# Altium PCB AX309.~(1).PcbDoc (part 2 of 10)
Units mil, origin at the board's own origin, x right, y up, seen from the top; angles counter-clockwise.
Board outline 5185 x 3614 mil, 4 copper layers (Top Layer, GND, Mid-Layer 1, Bottom Layer); 191 components, 352 nets, 1106 pads, 425 vias.
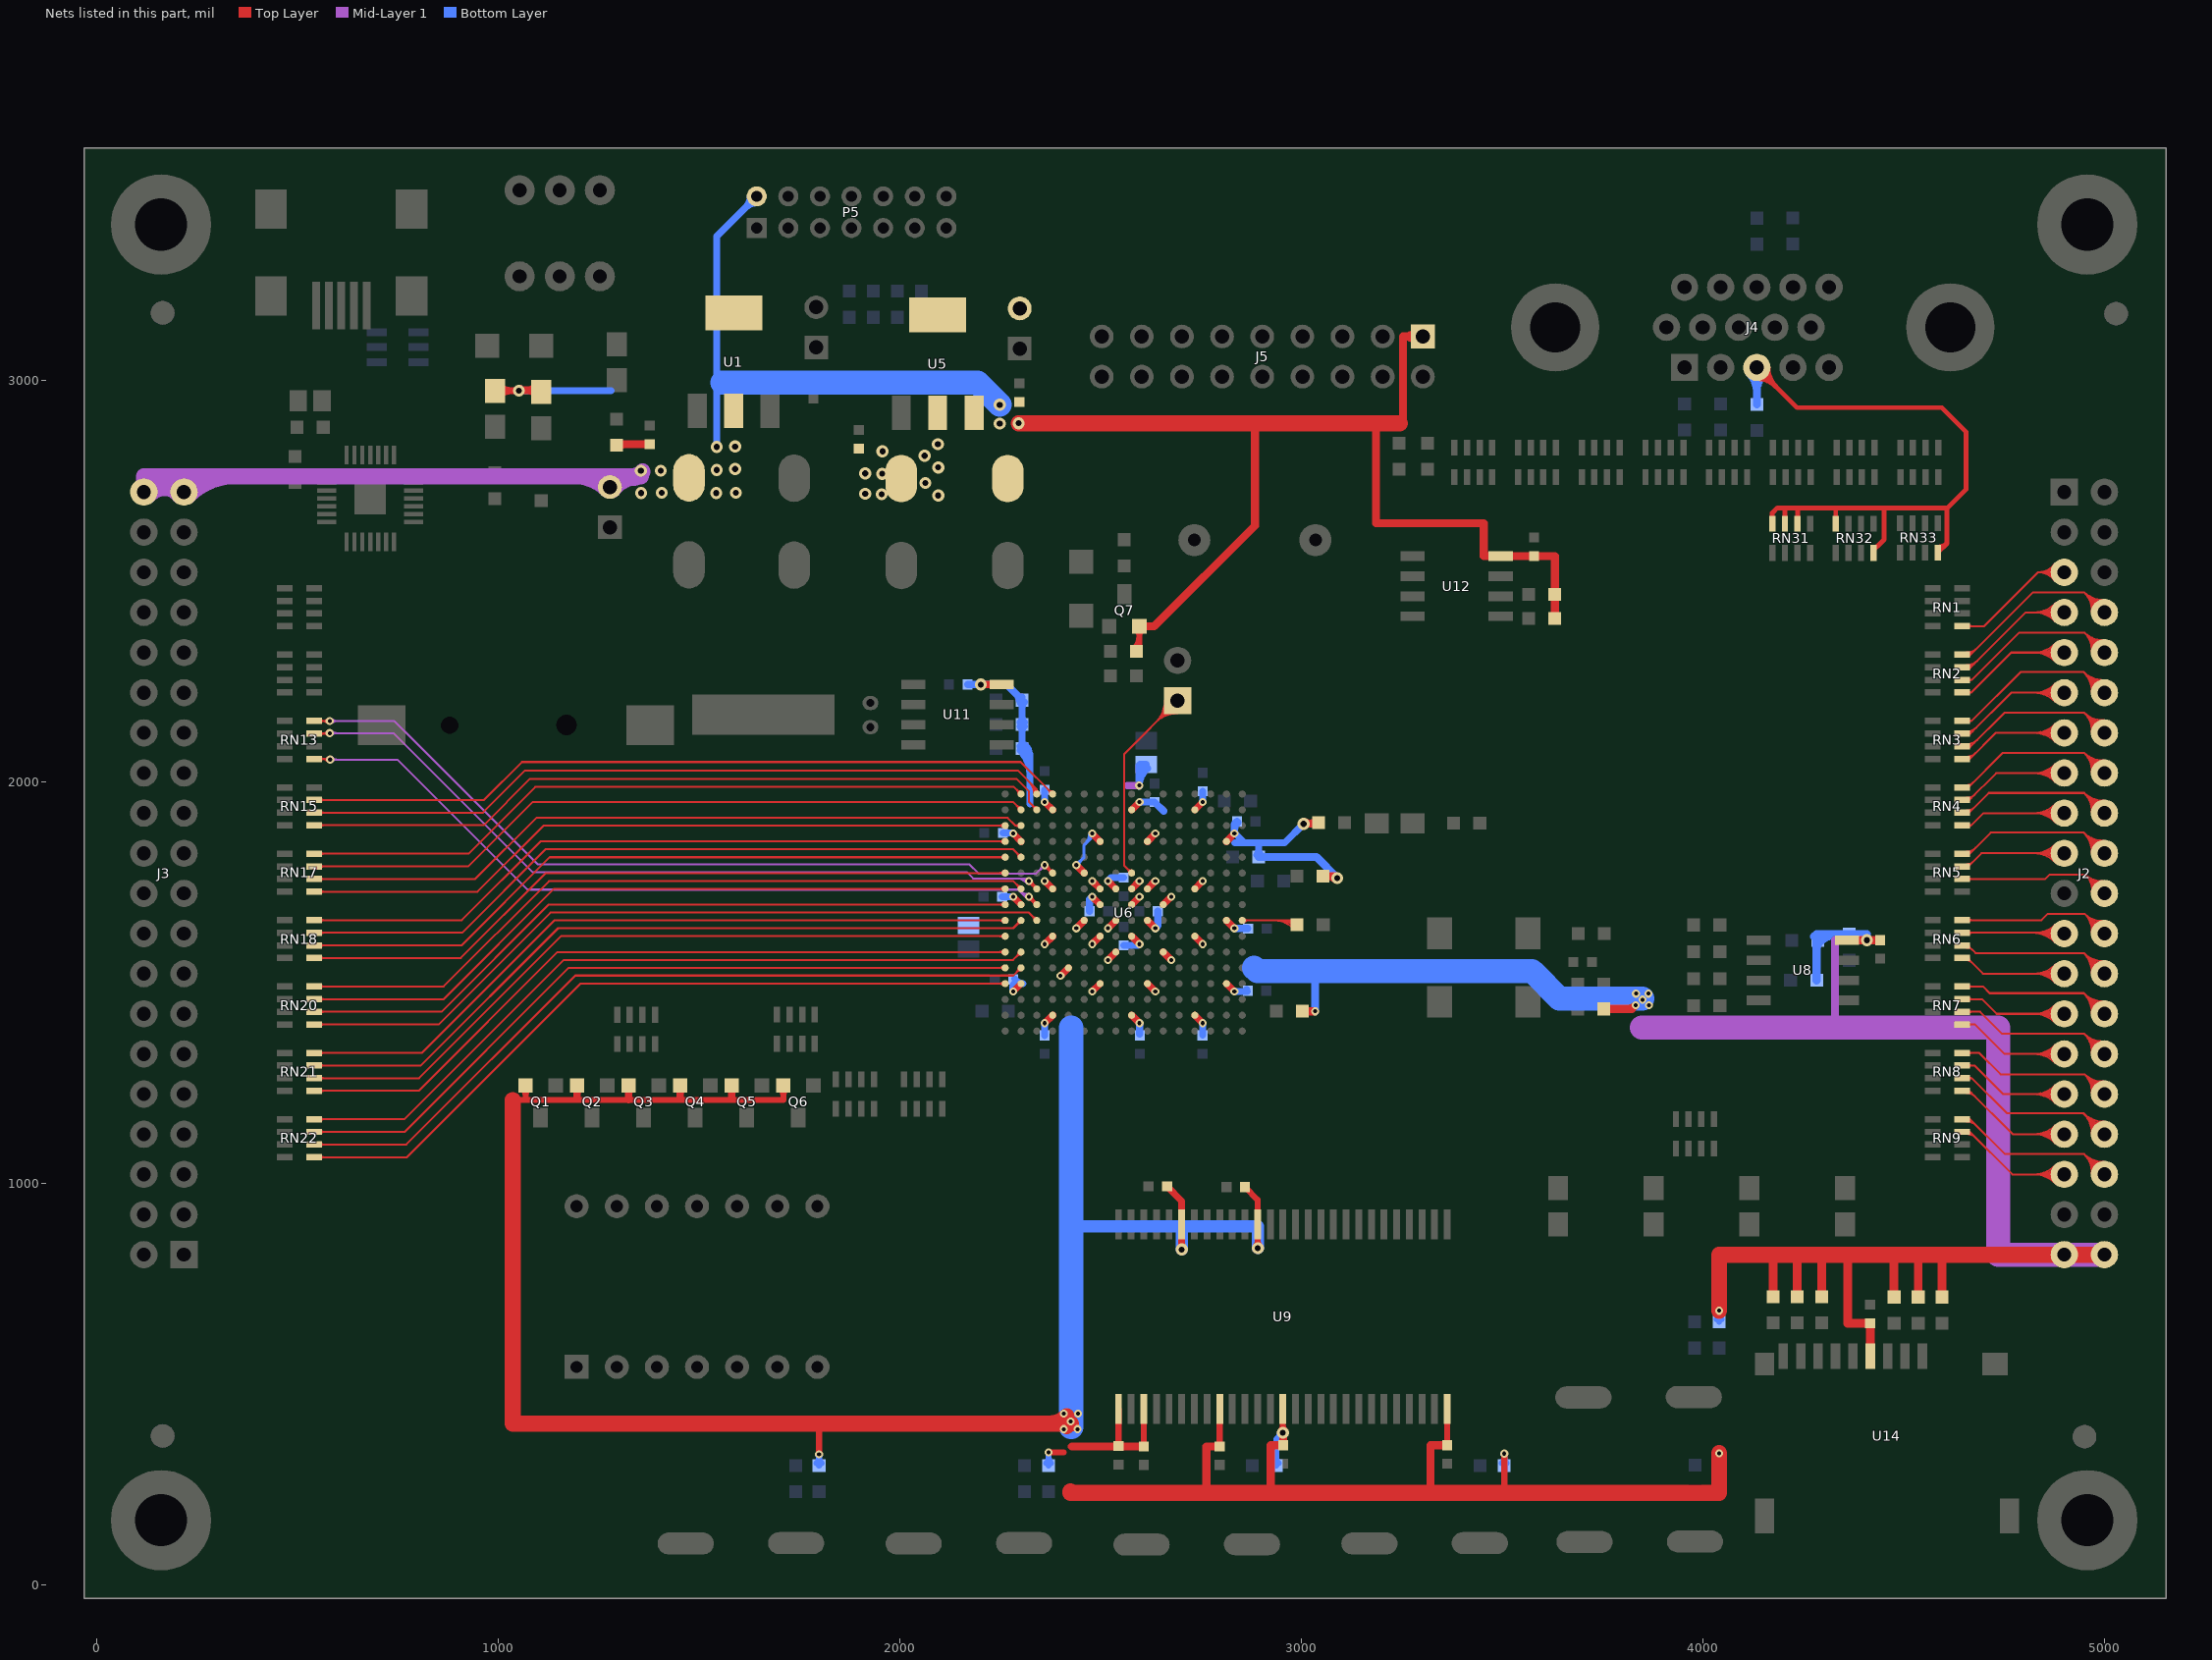
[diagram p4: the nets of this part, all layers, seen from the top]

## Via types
v1: diameter 20, hole 10, Top Layer to Bottom Layer, 328 vias
v2: diameter 30, hole 15, Top Layer to Bottom Layer, 95 vias
v3: diameter 40, hole 20, Top Layer to Bottom Layer, 2 vias

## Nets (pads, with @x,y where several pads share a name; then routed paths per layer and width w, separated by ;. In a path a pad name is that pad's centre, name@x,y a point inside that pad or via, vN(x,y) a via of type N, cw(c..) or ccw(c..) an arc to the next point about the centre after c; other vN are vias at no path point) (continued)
_L16: J2.5 RN1.5 | length 615.7
  Top Layer w5: RN1.5@4646.15,2387.51 4701.51,2387.51 4835.65,2521.65 ; RN1.5@4661.76,2383.71 cw(c4670.94,2374.54) 4670.94,2387.51 cw(c4670.94,2400.49) RN1.5@4661.76,2391.31 ; J2.5@4876.36,2502.03 ccw(c4835.66,2469.63) 4835.66,2521.65 ; J2.5@4876.36,2541.27 cw(c4835.66,2573.68) 4835.66,2521.65 ; J2.5@4880.27,2505.15 ccw(c4846.03,2477.89) 4846.03,2521.65 ccw(c4846.03,2565.42) J2.5@4880.27,2538.16 ; J2.5@4884.18,2508.26 ccw(c4856.4,2486.14) 4856.4,2521.65 ccw(c4856.4,2557.16) J2.5@4884.18,2535.05 ; J2.5@4888.09,2511.38 ccw(c4866.77,2494.4) 4866.77,2521.65 ccw(c4866.77,2548.9) J2.5@4888.09,2531.93 ; J2.5@4901,2521.65 4835.65,2521.65
_M4: J2.32 RN8.8 | length 735.9
  Top Layer w5: RN8.8@4646.15,1324.38 4688.62,1324.38 4742,1271 4951.65,1271 ; RN8.8@4661.76,1320.58 cw(c4670.94,1311.4) 4670.94,1324.38 cw(c4670.94,1337.35) RN8.8@4661.76,1328.17 ; J2.32@4969.56,1223.63 ccw(c4908.14,1227.48) 4951.66,1271 ; J2.32@4974.55,1223.31 ccw(c4922.88,1226.55) 4959.49,1263.16 ccw(c4996.1,1299.78) J2.32@4999.34,1248.1 ; J2.32@4979.54,1223 ccw(c4937.62,1225.63) 4967.32,1255.33 ccw(c4997.02,1285.04) J2.32@4999.65,1243.11 ; J2.32@4984.53,1222.69 ccw(c4952.36,1224.7) 4975.15,1247.5 ccw(c4997.95,1270.3) J2.32@4999.97,1238.12 ; J2.32@4999.03,1253.09 cw(c4995.18,1314.52) 4951.66,1271 ; J2.32@5001,1221.65 4951.65,1271
_M5: J2.35 RN9.7 | length 702.2
  Top Layer w5: RN9.7@4646.15,1127.5 4665.5,1127.5 4771.35,1021.65 J2.35@4901,1021.65 ; RN9.7@4657.96,1122.13 cw(c4657.96,1090.96) 4680,1113 ; RN9.7@4657.96,1127.13 cw(c4657.96,1108.04) 4671.46,1121.54 ; J2.35@4878.73,999.38 ccw(c4824.95,945.61) 4824.95,1021.65 ccw(c4824.95,1097.7) J2.35@4878.73,1043.93 ; J2.35@4882.26,1002.92 ccw(c4837.02,957.68) 4837.02,1021.65 ccw(c4837.02,1085.63) J2.35@4882.26,1040.39 ; J2.35@4885.8,1006.45 ccw(c4849.09,969.75) 4849.09,1021.65 ccw(c4849.09,1073.56) J2.35@4885.8,1036.86 ; J2.35@4889.33,1009.99 ccw(c4861.17,981.82) 4861.17,1021.65 ccw(c4861.17,1061.49) J2.35@4889.33,1033.32
_M15: J2.7 RN2.7 | length 748.9
  Top Layer w5: RN2.7@4646.15,2285.13 4668.13,2285.13 ; RN2.7@4657.96,2280.5 ccw(c4657.96,2293.88) 4667.42,2284.42 ; RN2.7@4657.96,2285.5 ccw(c4657.96,2310.95) 4675.96,2292.96 ; RN2.7@4657.96,2290.5 ccw(c4657.96,2328.02) 4684.49,2301.49 ; RN2.7@4662.4,2282.1 cw(c4668.13,2278.2) 4668.13,2285.13 ; RN2.7@4662.4,2288.16 ccw(c4668.13,2292.06) 4668.13,2285.13 ; J2.7@4878.73,2399.38 ccw(c4824.95,2345.61) 4824.95,2421.65 ccw(c4824.95,2497.7) J2.7@4878.73,2443.93 ; J2.7@4882.26,2402.92 ccw(c4837.02,2357.68) 4837.02,2421.65 ccw(c4837.02,2485.63) J2.7@4882.26,2440.39 ; J2.7@4885.8,2406.45 ccw(c4849.09,2369.75) 4849.09,2421.65 ccw(c4849.09,2473.56) J2.7@4885.8,2436.86 ; J2.7@4889.33,2409.99 ccw(c4861.17,2381.82) 4861.17,2421.65 ccw(c4861.17,2461.49) J2.7@4889.33,2433.32 ; J2.7@4901,2421.65 4804.65,2421.65 4668.13,2285.13
_M16: J2.8 RN2.8 | length 837.9
  Top Layer w5: RN2.8@4646.15,2316.62 4667.62,2316.62 ; RN2.8@4657.96,2312 ccw(c4657.96,2324.16) 4666.56,2315.56 ; RN2.8@4657.96,2317 ccw(c4657.96,2341.23) 4675.1,2324.1 ; RN2.8@4657.96,2322 ccw(c4657.96,2358.3) 4683.63,2332.63 ; RN2.8@4662.53,2313.79 cw(c4667.62,2310.62) 4667.62,2316.62 ; RN2.8@4662.53,2319.46 ccw(c4667.62,2322.63) 4667.62,2316.62 ; J2.8@4969.54,2423.15 ccw(c4904.9,2426.24) 4950.66,2472 ; J2.8@4974.53,2422.92 ccw(c4920.15,2425.51) 4958.65,2464.01 ccw(c4997.14,2502.5) J2.8@4999.74,2448.12 ; J2.8@4979.52,2422.68 ccw(c4935.41,2424.78) 4966.64,2456.02 ccw(c4997.87,2487.25) J2.8@4999.98,2443.13 ; J2.8@4984.52,2422.44 ccw(c4950.66,2424.06) 4974.63,2448.02 ccw(c4998.6,2471.99) J2.8@5000.21,2438.13 ; J2.8@4999.5,2453.12 cw(c4996.41,2517.76) 4950.66,2472 ; J2.8@5001,2421.65 4950.65,2472 ; 4667.62,2316.62 4823,2472 4950.65,2472
_N4: J2.36 RN9.8 | length 789.6
  Top Layer w5: RN9.8@4646.15,1159 4666,1159 ; RN9.8@4657.96,1153.63 cw(c4657.96,1121.24) 4680.86,1144.14 ; RN9.8@4657.96,1158.63 cw(c4657.96,1138.32) 4672.32,1152.68 ; RN9.8@4662.93,1156.95 cw(c4666,1155.67) 4666,1159 ; RN9.8@4662.93,1161.05 ccw(c4666,1162.33) 4666,1159 ; J2.36@4969.54,1023.15 ccw(c4904.9,1026.24) 4950.66,1072 ; J2.36@4974.53,1022.92 ccw(c4920.15,1025.51) 4958.65,1064.01 ccw(c4997.14,1102.5) J2.36@4999.74,1048.12 ; J2.36@4979.52,1022.68 ccw(c4935.41,1024.78) 4966.64,1056.02 ccw(c4997.87,1087.25) J2.36@4999.98,1043.13 ; J2.36@4984.52,1022.44 ccw(c4950.66,1024.06) 4974.63,1048.02 ccw(c4998.6,1071.99) J2.36@5000.21,1038.13 ; J2.36@4999.5,1053.12 cw(c4996.41,1117.76) 4950.66,1072 ; J2.36@5001,1021.65 4950.65,1072 ; 4666,1159 4753,1072 4950.65,1072
_N6: J2.34 RN8.6 | length 781.7
  Top Layer w5: RN8.6@4646.15,1261.38 4670.62,1261.38 ; RN8.6@4661.83,1257.65 cw(c4670.62,1249.17) 4670.62,1261.38 ; RN8.6@4661.83,1265.11 ccw(c4670.62,1273.6) 4670.62,1261.38 ; J2.34@4969.51,1122.26 ccw(c4898.29,1123.63) 4948.66,1174 ; J2.34@4974.5,1122.16 ccw(c4914.59,1123.32) 4956.96,1165.69 ccw(c4999.34,1208.06) J2.34@5000.49,1148.15 ; J2.34@4979.5,1122.07 ccw(c4930.89,1123) 4965.27,1157.38 ccw(c4999.65,1191.76) J2.34@5000.59,1143.15 ; J2.34@4984.5,1121.97 ccw(c4947.2,1122.69) 4973.58,1149.07 ccw(c4999.97,1175.46) J2.34@5000.68,1138.15 ; J2.34@5000.39,1153.15 cw(c4999.02,1224.37) 4948.66,1174 ; J2.34@5001,1121.65 4948.65,1174 ; 4670.62,1261.38 4758,1174 4948.65,1174
_N16: J2.10 RN2.6 | length 761.7
  Top Layer w5: RN2.6@4646.15,2253.63 4670.63,2253.63 ; RN2.6@4661.82,2249.9 cw(c4670.63,2241.38) 4670.63,2253.63 ; RN2.6@4661.82,2257.37 ccw(c4670.63,2265.88) 4670.63,2253.63 ; J2.10@4969.56,2323.63 ccw(c4908.14,2327.48) 4951.66,2371 ; J2.10@4974.55,2323.31 ccw(c4922.88,2326.55) 4959.49,2363.16 ccw(c4996.1,2399.78) J2.10@4999.34,2348.1 ; J2.10@4979.54,2323 ccw(c4937.62,2325.63) 4967.32,2355.33 ccw(c4997.02,2385.04) J2.10@4999.65,2343.11 ; J2.10@4984.53,2322.69 ccw(c4952.36,2324.7) 4975.15,2347.5 ccw(c4997.95,2370.3) J2.10@4999.97,2338.12 ; J2.10@4999.03,2353.09 cw(c4995.18,2414.52) 4951.66,2371 ; J2.10@5001,2321.65 4951.65,2371 ; 4670.63,2253.63 4788,2371 4951.65,2371
_P2: J2.31 RN8.7 | length 668.8
  Top Layer w5: RN8.7@4646.15,1292.88 4677.12,1292.88 4748.35,1221.65 J2.31@4901,1221.65 ; RN8.7@4661.76,1289.08 cw(c4670.94,1279.9) 4670.94,1292.88 cw(c4670.94,1305.85) RN8.7@4661.76,1296.68 ; J2.31@4878.73,1199.38 ccw(c4824.95,1145.61) 4824.95,1221.65 ccw(c4824.95,1297.7) J2.31@4878.73,1243.93 ; J2.31@4882.26,1202.92 ccw(c4837.02,1157.68) 4837.02,1221.65 ccw(c4837.02,1285.63) J2.31@4882.26,1240.39 ; J2.31@4885.8,1206.45 ccw(c4849.09,1169.75) 4849.09,1221.65 ccw(c4849.09,1273.56) J2.31@4885.8,1236.86 ; J2.31@4889.33,1209.99 ccw(c4861.17,1181.82) 4861.17,1221.65 ccw(c4861.17,1261.49) J2.31@4889.33,1233.32
_P6: J2.33 RN8.5 | length 698
  Top Layer w5: RN8.5@4646.15,1229.89 4664.11,1229.89 4772.35,1121.65 J2.33@4901,1121.65 ; RN8.5@4657.96,1224.51 cw(c4657.96,1196.69) 4677.64,1216.36 ; RN8.5@4657.96,1229.51 cw(c4657.96,1213.76) 4669.1,1224.9 ; J2.33@4878.73,1099.38 ccw(c4824.95,1045.61) 4824.95,1121.65 ccw(c4824.95,1197.7) J2.33@4878.73,1143.93 ; J2.33@4882.26,1102.92 ccw(c4837.02,1057.68) 4837.02,1121.65 ccw(c4837.02,1185.63) J2.33@4882.26,1140.39 ; J2.33@4885.8,1106.45 ccw(c4849.09,1069.75) 4849.09,1121.65 ccw(c4849.09,1173.56) J2.33@4885.8,1136.86 ; J2.33@4889.33,1109.99 ccw(c4861.17,1081.82) 4861.17,1121.65 ccw(c4861.17,1161.49) J2.33@4889.33,1133.32
_P15: J2.12 RN3.8 | length 784.3
  Top Layer w5: RN3.8@4646.15,2151.25 4670.25,2151.25 ; RN3.8@4661.91,2147.6 cw(c4670.25,2139.89) 4670.25,2151.25 ; RN3.8@4661.91,2154.9 ccw(c4670.25,2162.61) 4670.25,2151.25 ; J2.12@4969.52,2222.7 ccw(c4901.62,2224.96) 4949.66,2273 ; J2.12@4974.51,2222.53 ccw(c4917.39,2224.43) 4957.81,2264.85 ccw(c4998.22,2305.26) J2.12@5000.12,2248.14 ; J2.12@4979.51,2222.37 ccw(c4933.17,2223.91) 4965.96,2256.7 ccw(c4998.74,2289.49) J2.12@5000.29,2243.14 ; J2.12@4984.51,2222.2 ccw(c4948.94,2223.38) 4974.11,2248.55 ccw(c4999.27,2273.71) J2.12@5000.45,2238.14 ; J2.12@4999.95,2253.14 cw(c4997.7,2321.04) 4949.66,2273 ; J2.12@5001,2221.65 4949.65,2273 ; 4670.25,2151.25 4792,2273 4949.65,2273
_P16: J2.9 RN2.5 | length 676.1
  Top Layer w5: RN2.5@4646.15,2222.14 4669.14,2222.14 ; RN2.5@4662.16,2218.78 cw(c4669.14,2213.2) 4669.14,2222.14 ; RN2.5@4662.16,2225.49 ccw(c4669.14,2231.07) 4669.14,2222.14 ; J2.9@4878.73,2299.38 ccw(c4824.95,2245.61) 4824.95,2321.65 ccw(c4824.95,2397.7) J2.9@4878.73,2343.93 ; J2.9@4882.26,2302.92 ccw(c4837.02,2257.68) 4837.02,2321.65 ccw(c4837.02,2385.63) J2.9@4882.26,2340.39 ; J2.9@4885.8,2306.45 ccw(c4849.09,2269.75) 4849.09,2321.65 ccw(c4849.09,2373.56) J2.9@4885.8,2336.86 ; J2.9@4889.33,2309.99 ccw(c4861.17,2281.82) 4861.17,2321.65 ccw(c4861.17,2361.49) J2.9@4889.33,2333.32 ; J2.9@4901,2321.65 4768.65,2321.65 4669.14,2222.14
_R1: J2.30 RN7.6 | length 747.4
  Top Layer w5: RN7.6@4646.15,1426.76 4691.24,1426.76 4746,1372 4950.65,1372 ; RN7.6@4661.76,1422.96 cw(c4670.94,1413.78) 4670.94,1426.76 cw(c4670.94,1439.73) RN7.6@4661.76,1430.56 ; J2.30@4969.54,1323.15 ccw(c4904.9,1326.24) 4950.66,1372 ; J2.30@4974.53,1322.92 ccw(c4920.15,1325.51) 4958.65,1364.01 ccw(c4997.14,1402.5) J2.30@4999.74,1348.12 ; J2.30@4979.52,1322.68 ccw(c4935.41,1324.78) 4966.64,1356.02 ccw(c4997.87,1387.25) J2.30@4999.98,1343.13 ; J2.30@4984.52,1322.44 ccw(c4950.66,1324.06) 4974.63,1348.02 ccw(c4998.6,1371.99) J2.30@5000.21,1338.13 ; J2.30@4999.5,1353.12 cw(c4996.41,1417.76) 4950.66,1372 ; J2.30@5001,1321.65 4950.65,1372
_R2: J2.29 RN7.5 | length 669.8
  Top Layer w5: RN7.5@4646.15,1395.26 4678.74,1395.26 4752.35,1321.65 J2.29@4901,1321.65 ; RN7.5@4661.76,1391.46 cw(c4670.94,1382.29) 4670.94,1395.26 cw(c4670.94,1408.24) RN7.5@4661.76,1399.06 ; J2.29@4878.73,1299.38 ccw(c4824.95,1245.61) 4824.95,1321.65 ccw(c4824.95,1397.7) J2.29@4878.73,1343.93 ; J2.29@4882.26,1302.92 ccw(c4837.02,1257.68) 4837.02,1321.65 ccw(c4837.02,1385.63) J2.29@4882.26,1340.39 ; J2.29@4885.8,1306.45 ccw(c4849.09,1269.75) 4849.09,1321.65 ccw(c4849.09,1373.56) J2.29@4885.8,1336.86 ; J2.29@4889.33,1309.99 ccw(c4861.17,1281.82) 4861.17,1321.65 ccw(c4861.17,1361.49) J2.29@4889.33,1333.32
_R5: J2.28 RN7.8 | length 742.4
  Top Layer w5: RN7.8@4646.15,1489.75 4698.25,1489.75 4715,1473 4949.65,1473 ; RN7.8@4661.76,1485.95 cw(c4670.94,1476.78) 4670.94,1489.75 cw(c4670.94,1502.72) RN7.8@4661.76,1493.55 ; J2.28@4969.52,1422.7 ccw(c4901.62,1424.96) 4949.66,1473 ; J2.28@4974.51,1422.53 ccw(c4917.39,1424.43) 4957.81,1464.85 ccw(c4998.22,1505.26) J2.28@5000.12,1448.14 ; J2.28@4979.51,1422.37 ccw(c4933.17,1423.91) 4965.96,1456.7 ccw(c4998.74,1489.49) J2.28@5000.29,1443.14 ; J2.28@4984.51,1422.2 ccw(c4948.94,1423.38) 4974.11,1448.55 ccw(c4999.27,1473.71) J2.28@5000.45,1438.14 ; J2.28@4999.95,1453.14 cw(c4997.7,1521.04) 4949.66,1473 ; J2.28@5001,1421.65 4949.65,1473
_R7: J2.23 RN6.7 | length 637.3
  Top Layer w5: RN6.7@4646.15,1623.63 J2.23@4899.02,1623.63 ; RN6.7@4661.76,1619.83 cw(c4670.94,1610.65) 4670.94,1623.63 cw(c4670.94,1636.6) RN6.7@4661.76,1627.43 ; 4820.18,1623.63 cw(c4820.18,1540.84) J2.23@4878.73,1599.38 ; 4829.72,1623.63 ccw(c4829.72,1692.93) J2.23@4878.73,1643.93 ; 4832.25,1623.63 cw(c4832.25,1552.91) J2.23@4882.26,1602.92 ; 4841.79,1623.63 ccw(c4841.79,1680.86) J2.23@4882.26,1640.39 ; 4844.33,1623.63 cw(c4844.33,1564.98) J2.23@4885.8,1606.45 ; 4853.86,1623.63 ccw(c4853.86,1668.79) J2.23@4885.8,1636.86 ; 4856.4,1623.63 cw(c4856.4,1577.05) J2.23@4889.33,1609.99 ; 4865.93,1623.63 ccw(c4865.93,1656.72) J2.23@4889.33,1633.32
_R9: J2.19 RN5.7 | length 658.7
  Top Layer w5: RN5.7@4646.15,1789 4662,1789 4694.65,1821.65 J2.19@4901,1821.65 ; RN5.7@4657.96,1789.38 ccw(c4657.96,1800.04) RN5.7@4665.5,1792.5 ; RN5.7@4657.96,1794.38 ccw(c4657.96,1817.11) 4674.04,1801.04 ; J2.19@4878.73,1799.38 ccw(c4824.95,1745.61) 4824.95,1821.65 ccw(c4824.95,1897.7) J2.19@4878.73,1843.93 ; J2.19@4882.26,1802.92 ccw(c4837.02,1757.68) 4837.02,1821.65 ccw(c4837.02,1885.63) J2.19@4882.26,1840.39 ; J2.19@4885.8,1806.45 ccw(c4849.09,1769.75) 4849.09,1821.65 ccw(c4849.09,1873.56) J2.19@4885.8,1836.86 ; J2.19@4889.33,1809.99 ccw(c4861.17,1781.82) 4861.17,1821.65 ccw(c4861.17,1861.49) J2.19@4889.33,1833.32
_R12: J2.17 RN4.5 | length 648.1
  Top Layer w5: RN4.5@4646.15,1891.39 4669.39,1891.39 ; RN4.5@4662.1,1887.96 cw(c4669.39,1881.93) 4669.39,1891.39 ; RN4.5@4662.1,1894.81 ccw(c4669.39,1900.84) 4669.39,1891.39 ; J2.17@4878.73,1899.38 ccw(c4824.95,1845.61) 4824.95,1921.65 ccw(c4824.95,1997.7) J2.17@4878.73,1943.93 ; J2.17@4882.26,1902.92 ccw(c4837.02,1857.68) 4837.02,1921.65 ccw(c4837.02,1985.63) J2.17@4882.26,1940.39 ; J2.17@4885.8,1906.45 ccw(c4849.09,1869.75) 4849.09,1921.65 ccw(c4849.09,1973.56) J2.17@4885.8,1936.86 ; J2.17@4889.33,1909.99 ccw(c4861.17,1881.82) 4861.17,1921.65 ccw(c4861.17,1961.49) J2.17@4889.33,1933.32 ; J2.17@4901,1921.65 4699.65,1921.65 4669.39,1891.39
_R14: J2.16 RN4.8 | length 765.7
  Top Layer w5: RN4.8@4646.15,1985.88 4661.88,1985.88 4748,2072 4950.65,2072 ; RN4.8@4657.96,1986.25 ccw(c4657.96,1996.6) RN4.8@4665.28,1989.28 ; RN4.8@4657.96,1991.25 ccw(c4657.96,2013.67) 4673.82,1997.82 ; J2.16@4969.54,2023.15 ccw(c4904.9,2026.24) 4950.66,2072 ; J2.16@4974.53,2022.92 ccw(c4920.15,2025.51) 4958.65,2064.01 ccw(c4997.14,2102.5) J2.16@4999.74,2048.12 ; J2.16@4979.52,2022.68 ccw(c4935.41,2024.78) 4966.64,2056.02 ccw(c4997.87,2087.25) J2.16@4999.98,2043.13 ; J2.16@4984.52,2022.44 ccw(c4950.66,2024.06) 4974.63,2048.02 ccw(c4998.6,2071.99) J2.16@5000.21,2038.13 ; J2.16@4999.5,2053.12 cw(c4996.41,2117.76) 4950.66,2072 ; J2.16@5001,2021.65 4950.65,2072
_R15: J2.14 RN3.6 | length 813.5
  Top Layer w5: RN3.6@4646.15,2088.26 4668.26,2088.26 ; RN3.6@4657.96,2083.63 ccw(c4657.96,2097.32) 4667.64,2087.64 ; RN3.6@4657.96,2088.63 ccw(c4657.96,2114.39) 4676.18,2096.18 ; RN3.6@4657.96,2093.63 ccw(c4657.96,2131.46) 4684.71,2104.71 ; RN3.6@4662.37,2085.18 cw(c4668.26,2081.08) 4668.26,2088.26 ; RN3.6@4662.37,2091.33 ccw(c4668.26,2095.43) 4668.26,2088.26 ; J2.14@4969.54,2123.15 ccw(c4904.9,2126.24) 4950.66,2172 ; J2.14@4974.53,2122.92 ccw(c4920.15,2125.51) 4958.65,2164.01 ccw(c4997.14,2202.5) J2.14@4999.74,2148.12 ; J2.14@4979.52,2122.68 ccw(c4935.41,2124.78) 4966.64,2156.02 ccw(c4997.87,2187.25) J2.14@4999.98,2143.13 ; J2.14@4984.52,2122.44 ccw(c4950.66,2124.06) 4974.63,2148.02 ccw(c4998.6,2171.99) J2.14@5000.21,2138.13 ; J2.14@4999.5,2153.12 cw(c4996.41,2217.76) 4950.66,2172 ; J2.14@5001,2121.65 4950.65,2172 ; 4668.26,2088.26 4752,2172 4950.65,2172
_R16: J2.11 RN3.7 | length 715.2
  Top Layer w5: RN3.7@4646.15,2119.75 4666.75,2119.75 ; RN3.7@4657.96,2120.13 ccw(c4657.96,2142.26) 4673.61,2126.61 ; RN3.7@4657.96,2125.13 ccw(c4657.96,2159.33) 4682.15,2135.15 ; RN3.7@4662.74,2117.3 cw(c4666.75,2115.25) 4666.75,2119.75 ; RN3.7@4662.74,2122.2 ccw(c4666.75,2124.26) 4666.75,2119.75 ; J2.11@4878.73,2199.38 ccw(c4824.95,2145.61) 4824.95,2221.65 ccw(c4824.95,2297.7) J2.11@4878.73,2243.93 ; J2.11@4882.26,2202.92 ccw(c4837.02,2157.68) 4837.02,2221.65 ccw(c4837.02,2285.63) J2.11@4882.26,2240.39 ; J2.11@4885.8,2206.45 ccw(c4849.09,2169.75) 4849.09,2221.65 ccw(c4849.09,2273.56) J2.11@4885.8,2236.86 ; J2.11@4889.33,2209.99 ccw(c4861.17,2181.82) 4861.17,2221.65 ccw(c4861.17,2261.49) J2.11@4889.33,2233.32 ; J2.11@4901,2221.65 4768.65,2221.65 4666.75,2119.75
_T4: J2.27 RN7.7 | length 654.4
  Top Layer w5: RN7.7@4646.15,1458.25 4695.75,1458.25 4732.35,1421.65 J2.27@4901,1421.65 ; RN7.7@4661.76,1454.45 cw(c4670.94,1445.28) 4670.94,1458.25 cw(c4670.94,1471.23) RN7.7@4661.76,1462.05 ; J2.27@4878.73,1399.38 ccw(c4824.95,1345.61) 4824.95,1421.65 ccw(c4824.95,1497.7) J2.27@4878.73,1443.93 ; J2.27@4882.26,1402.92 ccw(c4837.02,1357.68) 4837.02,1421.65 ccw(c4837.02,1485.63) J2.27@4882.26,1440.39 ; J2.27@4885.8,1406.45 ccw(c4849.09,1369.75) 4849.09,1421.65 ccw(c4849.09,1473.56) J2.27@4885.8,1436.86 ; J2.27@4889.33,1409.99 ccw(c4861.17,1381.82) 4861.17,1421.65 ccw(c4861.17,1461.49) J2.27@4889.33,1433.32
_T5: J2.25 RN6.5 | length 655.4
  Top Layer w5: RN6.5@4646.15,1560.64 4659.36,1560.64 4698.35,1521.65 J2.25@4901,1521.65 ; RN6.5@4657.96,1555.26 cw(c4657.96,1538.9) 4669.53,1550.47 ; RN6.5@4663.33,1560.64 ccw(c4672.92,1560.64) 4666.14,1553.86 ; J2.25@4878.73,1499.38 ccw(c4824.95,1445.61) 4824.95,1521.65 ccw(c4824.95,1597.7) J2.25@4878.73,1543.93 ; J2.25@4882.26,1502.92 ccw(c4837.02,1457.68) 4837.02,1521.65 ccw(c4837.02,1585.63) J2.25@4882.26,1540.39 ; J2.25@4885.8,1506.45 ccw(c4849.09,1469.75) 4849.09,1521.65 ccw(c4849.09,1573.56) J2.25@4885.8,1536.86 ; J2.25@4889.33,1509.99 ccw(c4861.17,1481.82) 4861.17,1521.65 ccw(c4861.17,1561.49) J2.25@4889.33,1533.32
_T6: J2.26 RN6.6 | length 743.4
  Top Layer w5: RN6.6@4646.15,1592.13 4660.87,1592.13 4680,1573 4949.65,1573 ; RN6.6@4657.96,1586.76 cw(c4657.96,1566.77) 4672.1,1580.9 ; RN6.6@4663.34,1592.13 ccw(c4669.29,1592.13) RN6.6@4665.08,1587.92 ; J2.26@4969.52,1522.7 ccw(c4901.62,1524.96) 4949.66,1573 ; J2.26@4974.51,1522.53 ccw(c4917.39,1524.43) 4957.81,1564.85 ccw(c4998.22,1605.26) J2.26@5000.12,1548.14 ; J2.26@4979.51,1522.37 ccw(c4933.17,1523.91) 4965.96,1556.7 ccw(c4998.74,1589.49) J2.26@5000.29,1543.14 ; J2.26@4984.51,1522.2 ccw(c4948.94,1523.38) 4974.11,1548.55 ccw(c4999.27,1573.71) J2.26@5000.45,1538.14 ; J2.26@4999.95,1553.14 cw(c4997.7,1621.04) 4949.66,1573 ; J2.26@5001,1521.65 4949.65,1573
_T7: J2.24 RN6.8 | length 709
  Top Layer w5: RN6.8@4646.15,1655.12 4844.12,1655.12 4859,1670 4952.65,1670 ; RN6.8@4661.76,1651.33 cw(c4670.94,1642.15) 4670.94,1655.12 cw(c4670.94,1668.1) RN6.8@4661.76,1658.92 ; J2.24@4969.6,1624.11 ccw(c4911.33,1628.67) 4952.66,1670 ; J2.24@4974.58,1623.72 ccw(c4925.56,1627.56) 4960.33,1662.32 ccw(c4995.1,1697.09) J2.24@4998.93,1648.07 ; J2.24@4979.57,1623.33 ccw(c4939.79,1626.44) 4968,1654.65 ccw(c4996.21,1682.86) J2.24@4999.32,1643.09 ; J2.24@4984.55,1622.94 ccw(c4954.03,1625.33) 4975.68,1646.98 ccw(c4997.32,1668.62) J2.24@4999.71,1638.1 ; J2.24@4998.54,1653.06 cw(c4993.98,1711.33) 4952.66,1670 ; J2.24@5001,1621.65 4952.65,1670
_T9: J2.22 RN5.6 | length 685.2
  Top Layer w5: RN5.6@4646.15,1757.51 4853.51,1757.51 4864,1768 4954.65,1768 ; RN5.6@4661.76,1753.71 cw(c4670.94,1744.53) 4670.94,1757.51 cw(c4670.94,1770.48) RN5.6@4661.76,1761.31 ; J2.22@4969.69,1725.13 ccw(c4917.58,1730.92) 4954.66,1768 ; J2.22@4974.66,1724.58 ccw(c4930.82,1729.45) 4962.01,1760.64 ccw(c4993.2,1791.83) J2.22@4998.07,1747.99 ; J2.22@4979.63,1724.03 ccw(c4944.06,1727.98) 4969.37,1753.29 ccw(c4994.67,1778.59) J2.22@4998.63,1743.02 ; J2.22@4984.6,1723.48 ccw(c4957.3,1726.51) 4976.72,1745.93 ccw(c4996.15,1765.35) J2.22@4999.18,1738.05 ; J2.22@4997.52,1752.96 cw(c4991.73,1805.08) 4954.66,1768 ; J2.22@5001,1721.65 4954.65,1768
_T12: J2.20 RN5.8 | length 776.4
  Top Layer w5: RN5.8@4646.15,1820.5 4665.5,1820.5 4718,1873 4949.65,1873 ; RN5.8@4657.96,1820.87 ccw(c4657.96,1839.98) 4671.47,1826.47 ; RN5.8@4657.96,1825.87 ccw(c4657.96,1857.05) 4680,1835 ; J2.20@4969.52,1822.7 ccw(c4901.62,1824.96) 4949.66,1873 ; J2.20@4974.51,1822.53 ccw(c4917.39,1824.43) 4957.81,1864.85 ccw(c4998.22,1905.26) J2.20@5000.12,1848.14 ; J2.20@4979.51,1822.37 ccw(c4933.17,1823.91) 4965.96,1856.7 ccw(c4998.74,1889.49) J2.20@5000.29,1843.14 ; J2.20@4984.51,1822.2 ccw(c4948.94,1823.38) 4974.11,1848.55 ccw(c4999.27,1873.71) J2.20@5000.45,1838.14 ; J2.20@4999.95,1853.14 cw(c4997.7,1921.04) 4949.66,1873 ; J2.20@5001,1821.65 4949.65,1873
_T13: J2.18 RN4.6 | length 758
  Top Layer w5: RN4.6@4646.15,1922.88 4663.88,1922.88 4713,1972 4950.65,1972 ; RN4.6@4657.96,1923.26 ccw(c4657.96,1938.46) 4668.71,1927.71 ; RN4.6@4657.96,1928.26 ccw(c4657.96,1955.53) 4677.24,1936.24 ; J2.18@4969.54,1923.15 ccw(c4904.9,1926.24) 4950.66,1972 ; J2.18@4974.53,1922.92 ccw(c4920.15,1925.51) 4958.65,1964.01 ccw(c4997.14,2002.5) J2.18@4999.74,1948.12 ; J2.18@4979.52,1922.68 ccw(c4935.41,1924.78) 4966.64,1956.02 ccw(c4997.87,1987.25) J2.18@4999.98,1943.13 ; J2.18@4984.52,1922.44 ccw(c4950.66,1924.06) 4974.63,1948.02 ccw(c4998.6,1971.99) J2.18@5000.21,1938.13 ; J2.18@4999.5,1953.12 cw(c4996.41,2017.76) 4950.66,1972 ; J2.18@5001,1921.65 4950.65,1972
_T14: J2.15 RN4.7 | length 681.1
  Top Layer w5: RN4.7@4646.15,1954.38 4664.38,1954.38 4731,2021 J2.15@4900.35,2021 ; RN4.7@4657.96,1954.75 ccw(c4657.96,1971.15) 4669.56,1959.56 ; RN4.7@4657.96,1959.75 ccw(c4657.96,1988.22) 4678.09,1968.09 ; 4823.37,2021 ccw(c4823.37,2099.28) J2.15@4878.73,2043.93 ; 4826.53,2021 cw(c4826.53,1947.18) J2.15@4878.73,1999.38 ; 4835.45,2021 ccw(c4835.45,2087.21) J2.15@4882.26,2040.39 ; 4838.6,2021 cw(c4838.6,1959.25) J2.15@4882.26,2002.92 ; 4847.52,2021 ccw(c4847.52,2075.14) J2.15@4885.8,2036.86 ; 4850.67,2021 cw(c4850.67,1971.33) J2.15@4885.8,2006.45 ; 4859.59,2021 ccw(c4859.59,2063.07) J2.15@4889.33,2033.32 ; 4862.74,2021 cw(c4862.74,1983.4) J2.15@4889.33,2009.99
_T15: J2.13 RN3.5 | length 686.3
  Top Layer w5: RN3.5@4646.15,2056.76 4665.76,2056.76 4730.65,2121.65 J2.13@4901,2121.65 ; RN3.5@4657.96,2057.14 ccw(c4657.96,2076.87) 4671.92,2062.92 ; RN3.5@4657.96,2062.14 ccw(c4657.96,2093.94) 4680.45,2071.45 ; J2.13@4878.73,2099.38 ccw(c4824.95,2045.61) 4824.95,2121.65 ccw(c4824.95,2197.7) J2.13@4878.73,2143.93 ; J2.13@4882.26,2102.92 ccw(c4837.02,2057.68) 4837.02,2121.65 ccw(c4837.02,2185.63) J2.13@4882.26,2140.39 ; J2.13@4885.8,2106.45 ccw(c4849.09,2069.75) 4849.09,2121.65 ccw(c4849.09,2173.56) J2.13@4885.8,2136.86 ; J2.13@4889.33,2109.99 ccw(c4861.17,2081.82) 4861.17,2121.65 ccw(c4861.17,2161.49) J2.13@4889.33,2133.32
A4: RN22.5 U6.A4 | length 1945.1
  Top Layer w5: RN22.5@541.15,1064.51 772.51,1064.51 1204.83,1496.83 U6.A4@2262.72,1496.83 ; RN22.5@556.76,1060.71 cw(c565.93,1051.54) 565.93,1064.51 cw(c565.93,1077.49) RN22.5@556.76,1068.31 ; U6.A4@2258.23,1492.34 ccw(c2247.37,1481.48) 2247.37,1496.83 ccw(c2247.37,1512.18) U6.A4@2258.23,1501.33
A5: RN22.7 U6.A5 | length 1935.4
  Top Layer w5: RN22.7@541.15,1127.5 766.5,1127.5 1175.2,1536.2 U6.A5@2262.72,1536.2 ; RN22.7@556.76,1123.7 cw(c565.93,1114.53) 565.93,1127.5 cw(c565.93,1140.48) RN22.7@556.76,1131.3 ; U6.A5@2258.23,1531.71 ccw(c2247.37,1520.85) 2247.37,1536.2 ccw(c2247.37,1551.55) U6.A5@2258.23,1540.7
A6: RN21.5 U6.A6 | length 1909.3
  Top Layer w5: RN21.5@541.15,1229.89 801.89,1229.89 1147.57,1575.57 U6.A6@2262.72,1575.57 ; RN21.5@556.76,1226.09 cw(c565.93,1216.91) 565.93,1229.89 cw(c565.93,1242.86) RN21.5@556.76,1233.69 ; U6.A6@2258.23,1571.08 ccw(c2247.37,1560.22) 2247.37,1575.57 ccw(c2247.37,1590.92) U6.A6@2258.23,1580.07
A7: RN21.6 U6.A7 | length 1912.5
  Top Layer w5: RN21.6@541.15,1261.38 802.38,1261.38 1155.94,1614.94 U6.A7@2262.72,1614.94 ; RN21.6@556.76,1257.58 cw(c565.93,1248.41) 565.93,1261.38 cw(c565.93,1274.36) RN21.6@556.76,1265.18 ; U6.A7@2258.23,1610.45 ccw(c2247.37,1599.59) 2247.37,1614.94 ccw(c2247.37,1630.3) U6.A7@2258.23,1619.44
A8: RN21.8 U6.A8 | length 1902.7
  Top Layer w5: RN21.8@541.15,1324.38 809.38,1324.38 1139.32,1654.32 U6.A8@2262.72,1654.32 ; RN21.8@556.76,1320.58 cw(c565.93,1311.4) 565.93,1324.38 cw(c565.93,1337.35) RN21.8@556.76,1328.17 ; U6.A8@2258.23,1649.82 ccw(c2247.37,1638.96) 2247.37,1654.32 ccw(c2247.37,1669.67) U6.A8@2258.23,1658.81
A9: RN20.6 U6.A9 | length 1876.6
  Top Layer w5: RN20.6@541.15,1426.76 858.76,1426.76 1125.68,1693.68 U6.A9@2262.72,1693.68 ; RN20.6@556.76,1422.96 cw(c565.93,1413.78) 565.93,1426.76 cw(c565.93,1439.73) RN20.6@556.76,1430.56 ; U6.A9@2258.23,1689.19 ccw(c2247.37,1678.33) 2247.37,1693.68 ccw(c2247.37,1709.04) U6.A9@2258.23,1698.18
A10: RN20.7 U6.A10 | length 1879.9
  Top Layer w5: RN20.7@541.15,1458.25 864.25,1458.25 1139.06,1733.06 U6.A10@2262.72,1733.06 ; RN20.7@556.76,1454.45 cw(c565.93,1445.28) 565.93,1458.25 cw(c565.93,1471.23) RN20.7@556.76,1462.05 ; U6.A10@2258.23,1728.56 ccw(c2247.37,1717.7) 2247.37,1733.06 ccw(c2247.37,1748.41) U6.A10@2258.23,1737.55
A11: RN18.5 U6.A11 | length 1853.8
  Top Layer w5: RN18.5@541.15,1560.64 906.64,1560.64 1118.43,1772.43 U6.A11@2262.72,1772.43 ; RN18.5@556.76,1556.84 cw(c565.93,1547.66) 565.93,1560.64 cw(c565.93,1573.61) RN18.5@556.76,1564.44 ; U6.A11@2258.23,1767.93 ccw(c2247.37,1757.08) 2247.37,1772.43 ccw(c2247.37,1787.78) U6.A11@2258.23,1776.92
A12: RN18.6 U6.A12 | length 1857.1
  Top Layer w5: RN18.6@541.15,1592.13 908.13,1592.13 1127.8,1811.8 U6.A12@2262.72,1811.8 ; RN18.6@556.76,1588.33 cw(c565.93,1579.16) 565.93,1592.13 cw(c565.93,1605.11) RN18.6@556.76,1595.93 ; U6.A12@2258.23,1807.3 ccw(c2247.37,1796.45) 2247.37,1811.8 ccw(c2247.37,1827.15) U6.A12@2258.23,1816.29
A13: RN18.8 U6.A13 | length 1847.3
  Top Layer w5: RN18.8@541.15,1655.12 909.12,1655.12 1105.17,1851.17 U6.A13@2262.72,1851.17 ; RN18.8@556.76,1651.33 cw(c565.93,1642.15) 565.93,1655.12 cw(c565.93,1668.1) RN18.8@556.76,1658.92 ; U6.A13@2258.23,1846.67 ccw(c2247.37,1835.82) 2247.37,1851.17 ccw(c2247.37,1866.52) U6.A13@2258.23,1855.66
A14: RN17.5 U6.A14 | length 1834.2
  Top Layer w5: RN17.5@541.15,1726.01 948.01,1726.01 1112.54,1890.54 U6.A14@2262.72,1890.54 ; RN17.5@556.76,1722.21 cw(c565.93,1713.04) 565.93,1726.01 cw(c565.93,1738.99) RN17.5@556.76,1729.81 ; U6.A14@2258.23,1886.04 ccw(c2247.37,1875.19) 2247.37,1890.54 ccw(c2247.37,1905.89) U6.A14@2258.23,1895.03
B5: RN22.6 U6.B5 | length 1987.8
  Top Layer w5: RN22.6@541.15,1096.01 771.01,1096.01 1192,1517 2282.89,1517 U6.B5@2302.09,1536.2 ; RN22.6@556.76,1092.21 cw(c565.93,1083.03) 565.93,1096.01 cw(c565.93,1108.98) RN22.6@556.76,1099.81 ; U6.B5@2295.74,1536.2 cw(c2280.39,1536.2) 2291.24,1525.35 cw(c2302.09,1514.5) U6.B5@2302.09,1529.85
B6: RN22.8 U6.B6 | length 1978
  Top Layer w5: RN22.8@541.15,1159 766,1159 1163,1556 2282.52,1556 U6.B6@2302.09,1575.57 ; RN22.8@556.76,1155.2 cw(c565.93,1146.03) 565.93,1159 cw(c565.93,1171.97) RN22.8@556.76,1162.8 ; U6.B6@2295.74,1575.57 cw(c2280.39,1575.57) 2291.24,1564.72 cw(c2302.09,1553.87) U6.B6@2302.09,1569.22
B8: RN21.7 U6.B8 | length 1955.1
  Top Layer w5: RN21.7@541.15,1292.88 806.88,1292.88 1149,1635 2282.78,1635 U6.B8@2302.09,1654.32 ; RN21.7@556.76,1289.08 cw(c565.93,1279.9) 565.93,1292.88 cw(c565.93,1305.85) RN21.7@556.76,1296.68 ; U6.B8@2295.74,1654.32 cw(c2280.39,1654.32) 2291.24,1643.46 cw(c2302.09,1632.61) U6.B8@2302.09,1647.96
B10: RN20.8 U6.B10 | length 1921.9
  Top Layer w5: RN20.8@541.15,1489.75 863.75,1489.75 1126,1752 2283.15,1752 U6.B10@2302.09,1733.06 ; RN20.8@556.76,1485.95 cw(c565.93,1476.78) 565.93,1489.75 cw(c565.93,1502.72) RN20.8@556.76,1493.55 ; U6.B10@2295.74,1733.06 ccw(c2280.39,1733.06) 2291.24,1743.91 ccw(c2302.09,1754.76) U6.B10@2302.09,1739.41
B12: RN18.7 U6.B12 | length 1900.1
  Top Layer w5: RN18.7@541.15,1623.63 909.63,1623.63 1118,1832 2281.89,1832 U6.B12@2302.09,1811.8 ; RN18.7@556.76,1619.83 cw(c565.93,1610.65) 565.93,1623.63 cw(c565.93,1636.6) RN18.7@556.76,1627.43 ; U6.B12@2295.74,1811.8 ccw(c2280.39,1811.8) 2291.24,1822.65 ccw(c2302.09,1833.5) U6.B12@2302.09,1818.15
B14: RN17.6 U6.B14 | length 1872.5
  Top Layer w5: RN17.6@541.15,1757.51 942.51,1757.51 1095,1910 2269,1910 2288.46,1890.54 ; RN17.6@556.76,1753.71 cw(c565.93,1744.53) 565.93,1757.51 cw(c565.93,1770.48) RN17.6@556.76,1761.31 ; U6.B14@2297.22,1886.45 ccw(c2288.47,1879.11) 2288.47,1890.54 ; U6.B14@2297.22,1894.62 cw(c2288.47,1901.96) 2288.47,1890.54 ; U6.B14@2302.09,1890.54 2288.46,1890.54
B15: RN17.7 U6.B15 | length 1879.6
  Top Layer w5: RN17.7@541.15,1789 925,1789 1085,1949 2283,1949 U6.B15@2302.09,1929.91 ; RN17.7@556.76,1785.2 cw(c565.93,1776.03) 565.93,1789 cw(c565.93,1801.98) RN17.7@556.76,1792.8 ; U6.B15@2295.74,1929.91 ccw(c2280.39,1929.91) 2291.24,1940.76 ccw(c2302.09,1951.61) U6.B15@2302.09,1936.26
B16: RN17.8 U6.B16 | length 1881.7
  Top Layer w5: RN17.8@541.15,1820.5 925.5,1820.5 1092,1987 2284.37,1987 U6.B16@2302.09,1969.28 ; RN17.8@556.76,1816.7 cw(c565.93,1807.53) 565.93,1820.5 cw(c565.93,1833.47) RN17.8@556.76,1824.3 ; U6.B16@2295.74,1969.28 ccw(c2280.39,1969.28) 2291.24,1980.13 ccw(c2302.09,1990.98) U6.B16@2302.09,1975.63
BLUE: C40.1 J4.3 RN31.2 RN31.3 RN31.4 RN32.4 RN32.8 RN33.8 | length 2006.7
  Top Layer w12: J4.3@4135,3004 cw(c4135,2936.4) 4182.8,2984.2 cw(c4230.6,3032) J4.3@4163,3032 ; J4.3@4135,3016 cw(c4135,2977.37) 4162.31,3004.69 cw(c4189.63,3032) J4.3@4151,3032 ; J4.3@4135,3032 4235,2932 4596,2932 4656,2872 4656,2728 4609,2681 4609,2593.85 ; RN31.4@4173.51,2643 4173.51,2669.51 4186,2682 4452,2682 ; RN31.3@4205.01,2643 4205.01,2678.99 ; RN31.2@4236.5,2643 4236.5,2680.5 ; RN32.4@4331.51,2643 4331.51,2678.51 ; RN32.8@4426,2569.85 4426,2577 4452,2603 4452,2682 ; RN32.8@4426,2583.54 ccw(c4426,2599.31) 4437.16,2588.16 ; RN33.8@4585.85,2572.54 ccw(c4585.91,2576.82) RN33.8@4588.94,2573.79 ; RN33.8@4586,2570.85 4609,2593.85 ; RN33.8@4586.03,2584.53 ccw(c4586.5,2616.34) 4609,2593.85 ; 4608,2682 4452,2682
  Bottom Layer w20: J4.3@4118.03,3015.03 cw(c4077.06,2974.06) 4135,2974.06 cw(c4192.94,2974.06) J4.3@4151.97,3015.03 ; C40.1@4135,2940 J4.3@4135,3032
BUZZER: CB1.1 U6.J11 | length 880.6
  Top Layer w5: U6.J11@2571.33,1772.43 ccw(c2555.98,1772.43) 2566.83,1783.28 ccw(c2577.68,1794.13) U6.J11@2577.68,1778.78 ; U6.J11@2577.68,1772.43 2559,1791.11 2559,2069 CB1.1@2692,2202 ; CB1.1@2660.5,2202 cw(c2584.45,2202) 2638.23,2148.23 cw(c2692,2094.45) CB1.1@2692,2170.5 ; CB1.1@2665.5,2202 cw(c2601.52,2202) 2646.76,2156.76 cw(c2692,2111.52) CB1.1@2692,2175.5 ; CB1.1@2670.5,2202 cw(c2618.59,2202) 2655.3,2165.3 cw(c2692,2128.59) CB1.1@2692,2180.5 ; CB1.1@2675.5,2202 cw(c2635.67,2202) 2663.83,2173.83 cw(c2692,2145.67) CB1.1@2692,2185.5
C8: RN20.5 U6.C8 | length 1968.4
  Top Layer w5: RN20.5@541.15,1395.26 851.26,1395.26 1130,1674 2321.78,1674 U6.C8@2341.46,1654.32 ; RN20.5@556.76,1391.46 cw(c565.93,1382.29) 565.93,1395.26 cw(c565.93,1408.24) RN20.5@556.76,1399.06 ; U6.C8@2335.11,1654.32 ccw(c2319.76,1654.32) 2330.61,1665.17 ccw(c2341.46,1676.02) U6.C8@2341.46,1660.67
C9: RN13.5 U6.C9 | length 2248.9
  Top Layer w5: RN13.5@541.15,2056.76 v1@579.24,2056.76 ; RN13.5@556.76,2052.96 cw(c565.93,2043.79) 565.93,2056.76 cw(c565.93,2069.74) RN13.5@556.76,2060.56 ; RN13.5@558.64,2056.76 cw(c558.64,2032.64) v1@575.7,2049.7 ; 567.15,2056.76 ccw(c567.15,2068.85) v1@575.7,2060.3 ; 570.71,2056.76 cw(c570.71,2044.71) v1@579.23,2053.23 ; v1@2320.77,1705.94 cw(c2318.06,1685.96) U6.C9@2335.52,1696.04 ; v1@2321.44,1710.89 cw(c2319.79,1698.73) 2330.42,1704.87 ; v1@2321.78,1705.87 cw(c2321.78,1687.76) 2334.58,1700.57 cw(c2347.39,1713.37) v1@2329.28,1713.37 ; v1(2321.78,1713.37) U6.C9@2341.46,1693.68 ; v1@2323.75,1706.13 cw(c2325.56,1699.47) 2331.54,1702.92 ; v1@2324.26,1713.71 ccw(c2336.42,1715.36) 2330.28,1704.73 ; v1@2329.02,1711.4 ccw(c2335.68,1709.59) 2332.23,1703.61 ; v1@2329.21,1714.38 ccw(c2349.19,1717.09) U6.C9@2339.11,1699.63 ; U6.C9@2335.11,1693.68 ccw(c2319.76,1693.68) 2330.61,1704.54 ccw(c2341.46,1715.39) U6.C9@2341.46,1700.04 ; v1@2323.72,1706.13 cw(c2325.55,1699.3) 2329.08,1705.42 ccw(c2325.55,1699.3) v1@2323.72,1706.13 ; v1@2329.02,1711.43 ccw(c2335.85,1709.6) 2329.73,1706.07 cw(c2335.85,1709.6) v1@2329.02,1711.43
  Mid-Layer 1 w5: v1(581,2055) 749,2055 1073,1731 2295,1731 ; v1@586.3,2049.7 cw(c599.11,2036.89) 599.11,2055 cw(c599.11,2073.11) v1@586.3,2060.3 ; 2302.95,1723.05 ccw(c2320.37,1740.48) v1@2321.65,1715.87 ; 2310.89,1715.11 ccw(c2321.16,1725.37) v1@2321.91,1710.87 ; v1@2321.39,1720.86 cw(c2319.59,1755.59) 2295,1731 ; v1(2321.78,1713.37) 2312.63,1713.37 2295,1731
C10: RN13.7 U6.C10 | length 2253.7
  Top Layer w5: RN13.7@541.15,2119.75 v1@578.75,2119.75 ; RN13.7@556.76,2115.95 cw(c565.93,2106.78) 565.93,2119.75 cw(c565.93,2132.73) RN13.7@556.76,2123.55 ; RN13.7@558.89,2119.75 ccw(c558.89,2142.11) v1@574.7,2126.3 ; 564.9,2119.75 cw(c564.9,2105.9) v1@574.7,2115.7 ; v1@2320.77,1745.31 cw(c2318.06,1725.33) U6.C10@2335.52,1735.41 ; v1@2321.44,1750.26 cw(c2319.79,1738.1) 2330.42,1744.24 ; v1@2321.78,1745.24 cw(c2321.78,1727.13) 2334.58,1739.94 cw(c2347.39,1752.74) v1@2329.28,1752.74 ; v1(2321.78,1752.74) U6.C10@2341.46,1733.06 ; v1@2323.75,1745.5 cw(c2325.56,1738.84) 2331.54,1742.29 ; v1@2324.26,1753.08 ccw(c2336.42,1754.73) 2330.28,1744.1 ; v1@2329.02,1750.77 ccw(c2335.68,1748.96) 2332.23,1742.98 ; v1@2329.21,1753.75 ccw(c2349.19,1756.46) U6.C10@2339.11,1739 ; U6.C10@2335.11,1733.06 ccw(c2319.76,1733.06) 2330.61,1743.91 ccw(c2341.46,1754.76) U6.C10@2341.46,1739.41 ; v1@2323.72,1745.5 cw(c2325.55,1738.67) 2329.08,1744.79 ccw(c2325.55,1738.67) v1@2323.72,1745.5 ; v1@2329.02,1750.8 ccw(c2335.85,1748.97) 2329.73,1745.44 cw(c2335.85,1748.97) v1@2329.02,1750.8
  Mid-Layer 1 w5: v1(580,2121) 739,2121 1085,1775 2167,1775 2183,1759 2315.52,1759 v1(2321.78,1752.74) ; v1@585.3,2115.7 cw(c598.11,2102.89) 598.11,2121 cw(c598.11,2139.11) v1@585.3,2126.3 ; 2288.56,1759 cw(c2288.56,1719.52) v1@2316.48,1747.44 ; 2300.63,1759 cw(c2300.63,1731.6) v1@2320.01,1750.97 ; 2312.7,1759 cw(c2312.7,1743.67) v1@2323.55,1754.51
C15: RN15.5 U6.C15 | length 1940.2
  Top Layer w5: RN15.5@541.15,1891.39 963.39,1891.39 1079,2007 2291,2007 2322,1976 2322,1949.37 U6.C15@2341.46,1929.91 ; RN15.5@556.76,1887.59 cw(c565.93,1878.41) 565.93,1891.39 cw(c565.93,1904.36) RN15.5@556.76,1895.19 ; U6.C15@2335.11,1929.91 ccw(c2319.76,1929.91) 2330.61,1940.76 ccw(c2341.46,1951.61) U6.C15@2341.46,1936.26
C16: RN15.6 U6.C16 | length 1980.9
  Top Layer w5: RN15.6@541.15,1922.88 961.88,1922.88 1067,2028 2294,2028 2341.46,1980.54 ; RN15.6@556.76,1919.08 cw(c565.93,1909.91) 565.93,1922.88 cw(c565.93,1935.86) RN15.6@556.76,1926.68 ; 2322.65,1999.35 cw(c2292.57,1969.28) U6.C16@2335.11,1969.28 ; 2331.18,1990.82 cw(c2309.64,1969.28) U6.C16@2340.11,1969.28 ; U6.C16@2338.18,1974.72 ccw(c2334.67,1980.53) 2341.46,1980.53 ; 2339.72,1982.28 cw(c2326.71,1969.28) U6.C16@2345.11,1969.28 ; U6.C16@2341.46,1969.28 2341.46,1980.54 ; U6.C16@2344.75,1974.72 cw(c2348.25,1980.53) 2341.46,1980.53
CLK: R3.1 U6.T8 | length 321.3
  Top Layer w5: U6.T8@2853.28,1654.32 2979.68,1654.32 R3.1@2990,1644 ; U6.T8@2857.77,1649.82 cw(c2868.63,1638.96) 2868.63,1654.32 cw(c2868.63,1669.67) U6.T8@2857.77,1658.81 ; 2932.51,1654.31 cw(c2932.51,1586.51) R3.1@2980.45,1634.45 ; 2944.58,1654.32 cw(c2944.58,1598.58) R3.1@2983.99,1637.99 ; 2956.65,1654.31 cw(c2956.65,1610.65) R3.1@2987.53,1641.53 ; 2968.72,1654.32 cw(c2968.72,1622.72) R3.1@2991.06,1645.06
D1V2: C5.1 C6.1 C7.1 C8.1 C9.1 C48.1 EC4.1 P4.2 U5.2 U5.4 U6.G7 U6.G9 U6.H8 U6.H10 U6.J7 U6.J9 U6.K8 U6.K10 | length 549.9
  Top Layer w17.72: v1(2479.26,1595.26) U6.G7@2498.94,1614.94 ; v1(2479.26,1713.37) U6.G9@2498.94,1693.68 ; v1(2518.63,1634.63) U6.H8@2538.32,1654.32 ; v1(2518.63,1752.74) U6.H10@2538.32,1733.06 ; U6.J7@2577.68,1614.94 v1(2597.37,1595.26) ; U6.J9@2577.68,1693.68 v1(2597.37,1713.37) ; U6.K8@2617.06,1654.32 v1(2636.74,1634.63) ; U6.K10@2617.06,1733.06 v1(2636.74,1752.74)
  Mid-Layer 1 w17.72: 2566.5,1990.5 v1(2596.5,1990.5)
  Bottom Layer w17.72: C6.1@2473,1677 2473,1707.11 v1(2479.26,1713.37) ; v1(2518.63,1752.74) 2526.89,1761 C8.1@2558,1761 ; C7.1@2558,1592 2594.11,1592 v1(2597.37,1595.26) ; 2586.75,1592 ccw(c2586.75,1605.88) v1@2596.56,1596.07 ; v1@2596.5,1989.06 cw(c2654.07,1989.06) C5.1@2617.1,2033.19 ; v1(2596.5,1990.5) 2596.5,2040.5 2599,2043 C5.1@2614,2043 ; v1(2636.74,1634.63) 2643,1640.89 C9.1@2643,1677
  other v2: 2096,2713 1955,2716 1914,2717 2064,2744 1956,2767 1914,2768 2096,2783 2062,2812 1957,2823 2095,2841
D3V3: C4.2 C10.1 C11.1 C12.1 C13.1 C14.1 C15.1 C16.1 C17.1 C18.1 C19.1 C20.1 C25.1 C27.1 C29.1 C30.1 C31.1 C32.1 C33.1 C34.1 C35.1 C36.1 C37.1 C43.1 C44.1 C49.1 EC5.1 EC6.1 J2.39 J2.40 J3.39 J3.40 J5.1 L1.1 LED7.1 LED8.1 P1.2 P5.2 Q1.2 Q2.2 Q3.2 Q4.2 Q5.2 Q6.2 Q7.2 R1.1 R9.2 R12.1 R13.2 R14.2 R15.2 R17.2 R18.1 R19.1 R23.1 R24.1 R25.1 R26.1 R27.1 R32.1 R35.1 R36.1 R37.1 R38.1 R41.1 R42.1 R43.1 R45.1 R47.1 R50.2 R52.1 U1.2 U1.4 U5.3 U6.B4 U6.B9 U6.B13 U6.D2 U6.D7 U6.D10 U6.D15 U6.E5 U6.F8 U6.F11 U6.G4 U6.G10 U6.G13 U6.H6 U6.J2 U6.J10 U6.J15 U6.K4 U6.K13 U6.L6 U6.L9 U6.N2 U6.N7 U6.N10 U6.N15 U6.R4 U6.R8 U6.R13 U8.8 U9.1 U9.3 U9.9 U9.14 U9.27 U9.43 U9.49 U11.8 U12.8 U14.4 | length 24756.2
  Top Layer w15: 1036,1207 1068,1207 ; Q1.2@1060.58,1235.58 cw(c1042.65,1217.65) 1068,1217.65 cw(c1093.35,1217.65) Q1.2@1075.42,1235.58 ; Q1.2@1068,1243 1068,1207 ; Q6.2@1702.58,1235.58 cw(c1684.65,1217.65) 1710,1217.65 cw(c1735.35,1217.65) Q6.2@1717.42,1235.58 ; Q6.2@1710,1243 1710,1207 1068,1207 ; v1(1799,324) 1799,401 ; v1(2371,329) 2408,329 ; C30.1@2545,345 U9.1@2545,437 ; R32.1@2583.99,2331.01 ccw(c2552.58,2362.42) 2597,2362.42 ; Q7.2@2589.58,2379.58 cw(c2571.65,2361.65) 2597,2361.65 cw(c2622.35,2361.65) Q7.2@2604.42,2379.58 ; R32.1@2597,2332 Q7.2@2597,2387 Q7.2@2606,2387 ; C29.1@2607.99,344.01 U9.3@2607.99,437 ; C31.1@2797,344 U9.9@2796.97,437 ; C35.1@2860,990 2891.46,958.54 U9.43@2891.46,897 v2@2891.46,838 ; v2@2886.7,843.3 ccw(c2875.2,854.8) 2891.46,854.8 ; 2891.46,857.42 ccw(c2911.42,857.42) v2@2897.3,843.3 ; v2@2949.15,383.3 ccw(c2936.34,396.11) 2954.45,396.11 ccw(c2972.56,396.11) v2@2959.75,383.3 ; v2(2954.45,378) U9.14@2954.45,437 ; C33.1@3363.9,347.1 U9.27@3363.9,437 ; v1(3506,326) 3506,228 3507,228
  Top Layer w17: C34.1@2666,992 2702.48,955.52 U9.49@2702.48,897 v2(2702.48,834.48) ; v2@2697.88,839.08 ccw(c2686.79,850.17) 2702.48,850.17 ccw(c2718.17,850.17) v2@2707.08,839.08
  Top Layer w17.72: LED7.1@992,2974 v2(1051,2974) LED8.1@1104,2974 ; LED7.1@1003.41,2962.59 cw(c1030.97,2935.03) 1030.97,2974 cw(c1030.97,3012.97) LED7.1@1003.41,2985.41 ; v2@1054.07,2979.32 ccw(c1066.88,3001.5) 1073.5,2976.76 ; v2@1063.2,2974 ccw(c1063.2,3019.8) LED8.1@1095.59,2987.41 ; 1072.86,2974 cw(c1072.86,2941.86) LED8.1@1095.59,2964.59 ; Q2.2@1189.94,1236.54 cw(c1174.33,1220.93) 1196.4,1220.93 cw(c1218.47,1220.93) Q2.2@1202.86,1236.54 ; 1196.4,1208.4 Q2.2@1196.4,1243 ; Q3.2@1318.34,1236.54 cw(c1302.73,1220.93) 1324.8,1220.93 cw(c1346.87,1220.93) Q3.2@1331.26,1236.54 ; 1324.8,1207.2 Q3.2@1324.8,1243 ; Q4.2@1446.74,1236.54 cw(c1431.13,1220.93) 1453.2,1220.93 cw(c1475.27,1220.93) Q4.2@1459.66,1236.54 ; 1453.2,1211.8 Q4.2@1453.2,1243 ; Q5.2@1575.14,1236.54 cw(c1559.53,1220.93) 1581.6,1220.93 cw(c1603.67,1220.93) Q5.2@1588.06,1236.54 ; 1581.6,1214.4 Q5.2@1581.6,1243 ; v2(2202,2242) U11.8@2254,2242 ; v1(2282.41,1477.15) U6.B4@2302.09,1496.83 ; v1(2282.41,1713.37) U6.B9@2302.09,1693.68 ; v1(2282.41,1870.85) U6.B13@2302.09,1851.17 ; v1(2361.15,1398.41) U6.D2@2380.83,1418.09 ; v1(2361.15,1595.26) U6.D7@2380.83,1614.94 ; v1(2361.15,1752.74) U6.D10@2380.83,1733.06 ; v1(2361.15,1949.59) U6.D15@2380.83,1929.91 ; v1(2400.52,1516.52) U6.E5@2420.2,1536.2 ; v1(2439.89,1634.63) U6.F8@2459.57,1654.32 ; v1(2439.89,1792.11) U6.F11@2459.57,1772.43 ; v1(2479.26,1477.15) U6.G4@2498.94,1496.83 ; v1(2479.26,1752.74) U6.G10@2498.94,1733.06 ; v1(2479.26,1870.85) U6.G13@2498.94,1851.17 ; v1(2518.63,1555.89) U6.H6@2538.32,1575.57 ; U6.J2@2577.68,1418.09 v1(2597.37,1398.41) ; U6.J10@2577.68,1733.06 v1(2597.37,1752.74) ; U6.J15@2577.68,1929.91 v1(2597.37,1949.59) ; U6.K4@2617.06,1496.83 v1(2636.74,1477.15) ; U6.K13@2617.06,1851.17 v1(2636.74,1870.85) ; U6.L6@2656.43,1575.57 v1(2676.11,1555.89) ; U6.L9@2656.43,1693.68 v1(2676.11,1713.37) ; U6.N2@2735.17,1418.09 v1(2754.85,1398.41) ; U6.N7@2735.17,1614.94 v1(2754.85,1595.26) ; U6.N10@2735.17,1733.06 v1(2754.85,1752.74) ; U6.N15@2735.17,1929.91 v1(2754.85,1949.59) ; U6.R4@2813.91,1496.83 v1(2833.59,1477.15) ; U6.R8@2813.91,1654.32 v1(2833.59,1634.63) ; U6.R13@2813.91,1851.17 v1(2833.59,1870.85) ; v2(3006,1895) R17.2@3043,1895 ; v2@3009.41,1900.11 ccw(c3021.3,1917.9) 3026.84,1897.23 ; v2@3018.52,1895 ccw(c3018.52,1922.48) R17.2@3037.95,1903.05
  Top Layer w20: R1.1@1295,2838 1295,2841 C44.1@1377,2841 ; R1.1@1299.24,2833.76 cw(c1316.73,2816.27) 1316.73,2841 ; 2429,344.01 C29.1@2607.99,344.01 ; Q7.2@2602.66,2381.34 cw(c2616.31,2367.69) 2616.31,2387 cw(c2616.31,2406.31) Q7.2@2602.66,2392.66 ; Q7.2@2606,2387 2634,2387 2885,2638 2885,2893 ; 2764,230 2764,344 C31.1@2797,344 ; 2924,228 2924,347 C32.1@2955,347 v2@2955,383.3 ; R9.2@3003,1428 v1(3035,1428) ; R50.2@3054,1765 3085,1765 v2(3090,1760) ; R50.2@3065.86,1765 cw(c3065.86,1735.86) v2@3086.46,1756.46 ; 3186,2893 3186,2644 3455,2644 3455,2562 U12.8@3497,2562 C37.1@3580,2562 3632,2562 R23.1@3632,2467 R24.1@3632,2407 ; 3254,2893 3254,3109.17 J5.1@3303,3109.17 ; J5.1@3289.19,3095.37 ccw(c3255.86,3062.03) 3255.86,3109.17 ccw(c3255.86,3156.32) J5.1@3289.19,3122.98 ; 3322,228 3322,347 C33.1@3364,347 ; L1.1@3754,1434 3824,1434 v1(3833,1443) cw(c3811.27,1464.73) 3811.27,1434 ; U8.8@4360,1605 v2(4409,1605) C4.2@4441.76,1605 ; R42.1@4537,716 4537,821.65
  Top Layer w22: R52.1@4176,717 4176,821.65 ; R45.1@4236,717 4236,821.65 ; R41.1@4297,717 4297,821.65 ; 4361,821.65 4361,651 C43.1@4417,651 4417.66,651 U14.4@4417.66,568.82 ; R43.1@4477,716 4477,821.65 ; R47.1@4596,716 4596,821.65
  Top Layer w40: 1036,1207 1036,401 1799,401 v1@2426,401 ; v2(2296,2893) 2885,2893 3186,2893 3246,2893 ; 2372.79,401 ccw(c2372.79,462.21) 2416.07,418.93 ; 2399.34,401 cw(c2399.34,377.34) v1@2416.07,394.07 ; 2425,232 2425,228 2764,228 ; 2764,230 2764,228 ; 3506,228 3322,228 2924,228 2764,228 ; 3507,228 4041,228 v1(4041,327) ; v1(4041,682) 4041,821.65 4176,821.65 4236,821.65 4297,821.65 4361,821.65 4477,821.65 4537,821.65 4596,821.65 J2.39@4901,821.65 J2.40@5001,821.65
  Mid-Layer 1 w20: 4330,1388 4330,1605 v2(4409,1605)
  Mid-Layer 1 w40: J3.40@117,2721.65 117,2761 ; J3.40@128.63,2713.86 cw(c217,2654.61) 217,2761 ; J3.40@139.01,2721.76 cw(c168.08,2683.6) J3.39@205.95,2713.06 ; 171.15,2746.25 cw(c199.98,2708.41) J3.39@237.52,2737.62 ; 191.98,2761 cw(c191.98,2704.88) J3.39@238.6,2736.13 ; J3.39@198.62,2740.04 cw(c249.22,2689.43) 249.22,2761 ; J3.39@205.37,2713.86 ccw(c117,2654.61) 117,2761 ; J3.39@217,2721.65 217,2761 ; J3.39@226.9,2711.75 cw(c345.79,2592.86) 345.79,2761 ; 1189.81,2761 cw(c1189.81,2645.81) P1.2@1271.26,2727.26 ; 1254.4,2753.28 cw(c1270.68,2739.98) P1.2@1270.68,2761 ; P1.2@1285.38,2727.97 cw(c1355,2671.11) 1355,2761 217,2761 ; P1.2@1286.38,2761 cw(c1286.38,2742.38) 1299.55,2755.55 ; 1333.27,2761 ccw(c1333.27,2796.73) v2@1358.54,2771.46 ; 1338.63,2756.61 ccw(c1329.8,2789.55) v2@1359.33,2772.5 ; 117,2761 217,2761
  Mid-Layer 1 w60: 3849,1388 4330,1388 4736,1388 4736,821.65 J2.39@4901,821.65 J2.40@5001,821.65
  Bottom Layer w8: v1(2439.89,1792.11) 2459,1811.22 2459,1842 2479.26,1862.26 v1(2479.26,1870.85) ; v1@2439.89,1798.11 ccw(c2439.89,1812.6) 2450.13,1802.35 ccw(c2460.37,1792.11) v1@2445.89,1792.11 ; 2462.94,1845.94 ccw(c2438.03,1870.85) v1@2473.26,1870.85 ; 2476.6,1859.6 ccw(c2465.34,1870.85) v1@2481.26,1870.85
  Bottom Layer w15: R38.1@1792.99,302.01 ccw(c1778.48,316.52) 1799,316.52 ccw(c1819.52,316.52) R38.1@1805.01,302.01 ; v1@1796.83,322.75 cw(c1785.88,316.43) 1798.1,313.15 ; R38.1@1799,296 v1(1799,324) ; 1799.9,313.15 cw(c1812.12,316.43) v1@1801.17,322.75 ; R37.1@2364.99,302.01 ccw(c2350.48,316.52) 2371,316.52 ccw(c2391.52,316.52) R37.1@2377.01,302.01 ; R37.1@2371,296 v1(2371,329) ; R36.1@2931.99,302.01 ccw(c2917.48,316.52) 2938,316.52 ccw(c2958.52,316.52) R36.1@2944.01,302.01 ; R36.1@2938,296 2938,361.55 v2(2954.45,378) ; v2@2946.95,378 cw(c2928.84,378) 2941.65,365.2 cw(c2954.45,352.39) v2@2954.45,370.5 ; R35.1@3499.99,302.01 ccw(c3485.48,316.52) 3506,316.52 ccw(c3526.52,316.52) R35.1@3512.01,302.01 ; v1@3503.83,324.75 cw(c3491.35,317.54) 3505.27,313.81 ; R35.1@3506,296 v1(3506,326) ; 3506.73,313.81 cw(c3520.65,317.54) v1@3508.17,324.75 ; R19.1@4034.99,303.01 ccw(c4020.48,317.52) 4041,317.52 ccw(c4061.52,317.52) R19.1@4047.01,303.01 ; R18.1@4034.99,660.01 ccw(c4020.48,674.52) 4041,674.52 ccw(c4061.52,674.52) R18.1@4047.01,660.01 ; v1@4038.83,325.75 cw(c4026.35,318.54) 4040.27,314.81 ; v1@4038.83,680.75 cw(c4027.88,674.43) 4040.1,671.15 ; R19.1@4041,297 v1(4041,327) ; R18.1@4041,654 v1(4041,682) ; 4041.73,314.81 cw(c4055.65,318.54) v1@4043.17,325.75 ; 4041.9,671.15 cw(c4054.12,674.43) v1@4043.17,680.75
  Bottom Layer w17.72: v2(1051,2974) 1281,2974 ; v2(1544,2834) 1544,3358.59 P5.2@1643.78,3458.37 ; P5.2@1627.64,3458.37 cw(c1588.67,3458.37) 1616.22,3430.81 cw(c1643.78,3403.26) P5.2@1643.78,3442.23 ; C36.1@2169,2242 v2(2202,2242) 2266,2242 R27.1@2305,2203 R25.1@2305,2143 R26.1@2305,2083 2324,2064 2324,1945 ; C14.1@2255.37,1713.37 v1(2282.41,1713.37) ; C13.1@2257,1872 v1@2281.26,1872 ; v1@2283,1477.74 2283,1494 C16.1@2286,1497 ; v1@2283.4,1477.71 cw(c2297.35,1485.65) C16.1@2286,1497 ; C16.1@2286.13,1508.86 ccw(c2307,1521.29) 2307,1497 C16.1@2286,1497 ; R27.1@2297.86,2203 ccw(c2280.62,2203) 2292.81,2215.19 ccw(c2305,2227.38) R27.1@2305,2210.14 ; R26.1@2299.95,2077.95 cw(c2241.89,2019.89) 2324,2019.89 ; R26.1@2299.95,2088.05 ccw(c2287.76,2100.24) 2305,2100.24 ccw(c2322.24,2100.24) R26.1@2310.05,2088.05 ; R25.1@2299.95,2137.95 cw(c2287.76,2125.76) 2305,2125.76 cw(c2322.24,2125.76) R25.1@2310.05,2137.95 ; R25.1@2299.95,2148.05 ccw(c2287.76,2160.24) 2305,2160.24 ccw(c2322.24,2160.24) R25.1@2310.05,2148.05 ; R27.1@2299.95,2197.95 cw(c2287.76,2185.76) 2305,2185.76 cw(c2322.24,2185.76) R27.1@2310.05,2197.95 ; R26.1@2304.8,2075.86 cw(c2304.26,2056.13) 2324,2056.13 ; R26.1@2305,2075.86 cw(c2305,2058.62) 2317.19,2070.81 cw(c2329.38,2083) R26.1@2312.14,2083 ; R26.1@2312.48,2090.48 cw(c2284.66,2062.66) 2324,2062.66 ; C15.1@2361.15,1368 v1(2361.15,1398.41) ; v1(2361.15,1949.59) C12.1@2361.15,1979.85 ; C17.1@2597.37,1370.63 v1(2597.37,1398.41) ; v1(2597.37,1949.59) C11.1@2634.41,1949.59 ; C11.1@2635,1949 2657.5,1926.5 ; C18.1@2754.85,1368.85 v1(2754.85,1398.41) ; v1@2755,1949.74 C10.1@2755,1976 ; v1(2833.59,1477.15) C27.1@2865.15,1477.15 ; v1(2833.59,1634.63) C25.1@2867.37,1634.63 ; v1@2833.59,1876.74 cw(c2864.26,1876.74) C20.1@2842.58,1898.42 ; 2835,1848 2858,1848 ; C20.1@2840,1901 2833.59,1894.59 v1(2833.59,1870.85) 2835.15,1870.85 2858,1848 ; 2853.74,1477.15 ccw(c2853.74,1492.26) C27.1@2864.42,1481.58 ; R12.1@2888.95,1817.05 ccw(c2876.76,1829.24) 2894,1829.24 ccw(c2911.24,1829.24) R12.1@2899.05,1817.05 ; R12.1@2894,1812 2894,1848 ; v2(3006,1895) 2959,1848 2894,1848 ; 2858,1848 2894,1848
  Bottom Layer w20: R12.1@2894,1812 3038,1812 v2(3090,1760) ; v1(3035,1428) 3035,1519 ; R15.2@4277.1,1613.9 cw(c4291.83,1599.17) 4291.83,1620 ; R14.2@4284,1505 4284,1620 R13.2@4365,1620 ; 4284,1582.27 cw(c4308.73,1582.27) 4291.24,1599.76 cw(c4340.11,1550.89) 4340.11,1620 ; v2@4405.23,1601.71 ccw(c4365,1566.6) R13.2@4365,1620 ; v2(4409,1605) 4409,1620 R13.2@4365,1620
  Bottom Layer w30: 2426.97,892 2702.48,892 ; v2(2702.48,834.48) 2702.48,892 ; v2(2892,838) 2892,892 2702.48,892
  Bottom Layer w40: P1.2@1262,2750 P1.2@1278,2734
  Bottom Layer w60: 1558,2994 2194,2994 v2(2249,2939) ; 2426.97,392 2426.97,892 2426.97,1387 ; 2883,1536 2891,1528 3575,1528 ; 3579,1524 3643,1460 v1@3850,1460
  other v1: 2409,387 2443,387 2426,406 2409,426 2444,426 3866,1443 3850,1457 3834,1472 3865,1472
  other v2: 1356,2719 1543,2719 1407,2720 1592,2720 1355,2775 1404.42,2775 1543.9,2776.68 1590,2779 1590,2835 2249,2892
D11: RN13.8 U6.D11 | length 2271.5
  Top Layer w5: RN13.8@541.15,2151.25 v1@579.75,2151.25 ; RN13.8@556.76,2147.45 cw(c565.93,2138.28) 565.93,2151.25 cw(c565.93,2164.22) RN13.8@556.76,2155.05 ; 561.29,2151.25 cw(c561.29,2132.29) v1@574.7,2145.7 ; 562.5,2151.25 ccw(c562.5,2168.5) v1@574.7,2156.3 ; v1@2360.14,1784.68 cw(c2357.43,1764.7) U6.D11@2374.89,1774.78 ; v1@2360.81,1789.63 cw(c2359.16,1777.47) 2369.79,1783.61 ; v1@2361.15,1784.61 cw(c2361.15,1766.5) 2373.95,1779.31 cw(c2386.76,1792.11) v1@2368.65,1792.11 ; v1(2361.15,1792.11) U6.D11@2380.83,1772.43 ; v1@2363.12,1784.87 cw(c2364.93,1778.21) 2370.91,1781.66 ; v1@2363.63,1792.45 ccw(c2375.79,1794.1) 2369.65,1783.47 ; v1@2368.58,1793.12 ccw(c2388.56,1795.83) U6.D11@2378.48,1778.37 ; 2371.6,1782.35 cw(c2375.05,1788.33) v1@2368.39,1790.14 ; U6.D11@2374.48,1772.43 ccw(c2359.13,1772.43) 2369.98,1783.28 ccw(c2380.83,1794.13) U6.D11@2380.83,1778.78 ; v1@2368.39,1790.17 ccw(c2375.22,1788.34) 2369.1,1784.81 cw(c2375.22,1788.34) v1@2368.39,1790.17 ; v1@2363.09,1784.87 cw(c2364.92,1778.04) 2368.45,1784.16 ccw(c2364.92,1778.04) v1@2363.09,1784.87
  Mid-Layer 1 w5: v1(580,2151) 741,2151 1098,1794 2173,1794 2196,1771 2340.04,1771 v1(2361.15,1792.11) ; v1@585.3,2145.7 cw(c598.11,2132.89) 598.11,2151 cw(c598.11,2169.11) v1@585.3,2156.3 ; v1@2353.65,1792.11 cw(c2335.54,1792.11) 2348.35,1779.31 cw(c2361.15,1766.5) v1@2361.15,1784.61
D16: RN15.7 U6.D16 | length 1956.4
  Top Layer w5: RN15.7@541.15,1954.38 964.38,1954.38 1059,2049 2301.11,2049 U6.D16@2380.83,1969.28 ; RN15.7@556.76,1950.58 cw(c565.93,1941.4) 565.93,1954.38 cw(c565.93,1967.35) RN15.7@556.76,1958.18 ; U6.D16@2374.48,1969.28 ccw(c2359.13,1969.28) 2369.98,1980.13 ccw(c2380.83,1990.98) U6.D16@2380.83,1975.63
